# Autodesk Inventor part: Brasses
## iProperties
Shininess: 77.0
Length Units: 11269
Angle Units: 11279
Time Units: 11290
Mass Units: 11283
Length Display Precision: 3
Angle Display Precision: 2
Created: 2002-02
Part Number: Brasses
Document SubType Name: Modeling
Designer: ***
Density: 1 g/cm^3
Density: 0.0
Volumn: 0.0
Area: 0.0
PropertySet Name: Model Information
Control State: 0
Master: False
Checked Out: False
Author: ***
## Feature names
1. Revolution1
2. Hole1
3. Extrusion1
4. Hole2
